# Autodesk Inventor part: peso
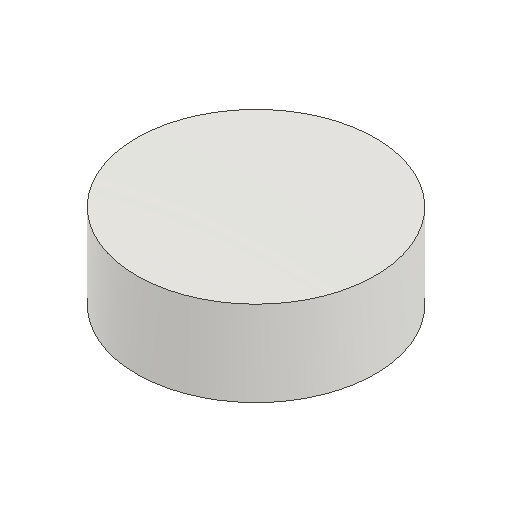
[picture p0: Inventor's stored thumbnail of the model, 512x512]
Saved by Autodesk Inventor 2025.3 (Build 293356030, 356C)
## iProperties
Created: 2025-11
Part Number: peso
Material: Acciaio
Document SubType Name: Modeling
Designer: R5800u
Density: 7.85 g/cm^3
Appearance: Acciaio
Mass: 755.259 g
Surface Area: 131.947 cm^2
Volume: 96.2113 cm^3
Author: R5800u
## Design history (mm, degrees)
sketch "Schizzo1"
  geometry: C1 r 35 at (0, 0); 1 further point
  constraints: 1 centre point, 1 coincident
  dimensions: "d0" = 70 diameter of C1
extrude "Estrusione1" new body sketch "Schizzo1" distance "d1" = 25; taper "d2" = 0 deg
node "Solido1"
